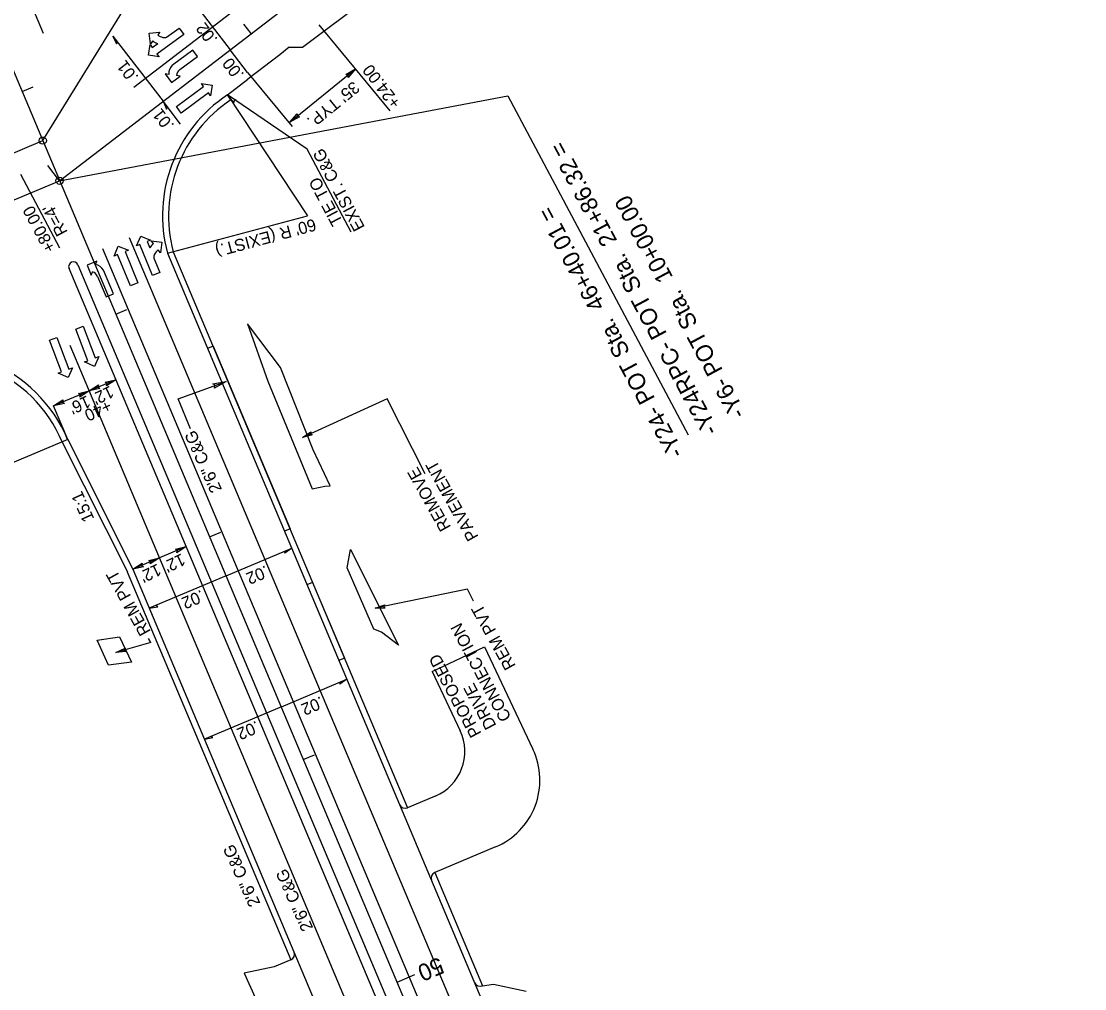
# Model space of a CAD drawing. Extents: x 2389694 to 2405615, y 546931 to 573532.
# Drawn here: x 2402756.3 to 2403196.8, y 570052.9 to 570453.5 of the extents above; entities that cross this region are included whole.
import ezdxf

# ---------------------------------------------------------------- set-up
doc = ezdxf.new("R2010")
doc.units = 0
for name, color, linetype in [('Old_Level_11', 7, 'Continuous'), ('Old_Level_3', 7, 'Continuous'), ('Prop Conc 2ft 6in Curb and Gutter', 7, 'Continuous'), ('Prop Conc 5in Monolithic Keyed In Island', 7, 'Continuous'), ('Prop Dimension', 7, 'Continuous'), ('Prop Dimension Text', 7, 'Continuous'), ('Prop DSN Text', 7, 'Continuous'), ('Prop EOT', 7, 'Continuous'), ('Prop Hatching', 7, 'Continuous'), ('Prop Horizontal Alignment', 7, 'Continuous'), ('Prop Horizontal Alignment Curve and Spiral Data', 7, 'Continuous'), ('Prop Horizontal Alignment Tick Large', 7, 'Continuous'), ('Prop Horizontal Alignment Tick Small', 7, 'Continuous'), ('Prop Lane Arrow Left Turn CELL', 7, 'Continuous'), ('Prop Lane Arrow Shared Rt and Thru CELL', 7, 'Continuous'), ('Prop Lane Arrow Through CELL', 7, 'Continuous'), ('Prop Lane Lines', 7, 'Continuous'), ('Prop Super Arrow 1 Lane CELL', 7, 'Continuous'), ('Prop Superelevation Label', 7, 'Continuous')]:
    doc.layers.add(name, color=color, linetype=linetype)

# ---------------------------------------------------------------- blocks, each defined once
blk = doc.blocks.new('TERM')
at = {"layer": 'Old_Level_11'}
blk.add_lwpolyline([(-0.01375, 0.00225), (0, 0), (-0.01375, -0.0025), (-0.012, 0)], close=True, dxfattribs=at)

msp = doc.modelspace()

# ---------------------------------------------------------------- linework, layer by layer
at = {"layer": 'Old_Level_3'}
for p, q in [((2402819.33, 570358.05), (2402916.31, 570127.82)), ((2402927.62, 570100.99), (2402947.36, 570054.13))]:
    msp.add_line(p, q, dxfattribs=at)
for centre, radius, start, end in [((2402874.85, 570372.92), 57.5, 123.4608, 194.9966), ((2402867.01, 570067.13), 2.5, 293.3106, 22.8448), ((2402946.41, 570056.44), 2.5, 202.8448, 292.379)]:
    msp.add_arc(centre, radius, start, end, dxfattribs=at)
at = {"layer": 'Prop Conc 2ft 6in Curb and Gutter'}
for p, q in [((2402843.14, 570420.89), (2402841.76, 570422.97)), ((2402835.78, 570318.99), (2402833.48, 570318.01)), ((2402835.78, 570318.99), (2402867.66, 570243.32)), ((2402773.33, 570279.21), (2402800.31, 570225.49)), ((2402867.66, 570243.32), (2402865.35, 570242.35)), ((2402800.27, 570225.56), (2402867.98, 570064.82)), ((2402877, 570221.15), (2402874.69, 570220.18)), ((2402877, 570221.15), (2402889.21, 570192.16)), ((2402890.22, 570189.76), (2402887.92, 570188.79)), ((2402889.21, 570192.16), (2402890.22, 570189.76))]:
    msp.add_line(p, q, dxfattribs=at)
msp.add_arc((2402720.27, 570257.04), 57.5, 22.8448, 112.8448, dxfattribs=at)
at = {"layer": 'Prop Conc 5in Monolithic Keyed In Island'}
for p, q in [((2402779.82, 570352.67), (2402944.82, 569961)), ((2402941.22, 569959.23), (2402776.13, 570351.12)), ((2402776.13, 570351.12), (2402776.13, 570351.12))]:
    msp.add_line(p, q, dxfattribs=at)
msp.add_arc((2402777.97, 570351.89), 2, 22.8448, 202.8424, dxfattribs=at)
at = {"layer": 'Prop Dimension'}
for p, q in [((2402879.62, 570452.02), (2402909.05, 570416.43)), ((2402850.07, 570432.19), (2402868.5, 570409.89)), ((2402867.6, 570411.63), (2402894.77, 570433.7)), ((2402841.76, 570422.97), (2402874.85, 570372.92)), ((2402874.73, 570400.48), (2402841.76, 570422.97)), ((2402893, 570366.11), (2402874.73, 570400.48)), ((2402816.89, 570357.39), (2402874.85, 570372.92)), ((2402795.54, 570305.04), (2402769.74, 570294.17)), ((2402821.34, 570297.09), (2402841.23, 570304.38)), ((2402826.5, 570284.66), (2402821.34, 570297.09)), ((2402907.87, 570297.12), (2402872.83, 570281.13)), ((2402923.7, 570266.05), (2402907.87, 570297.12)), ((2402775.57, 570280.33), (2402769.74, 570294.17)), ((2402775.57, 570280.33), (2402720.27, 570257.04)), ((2402824.66, 570235.93), (2402802.54, 570226.61)), ((2402941.22, 570218.32), (2402902.95, 570210.43)), ((2402943.73, 570213.38), (2402941.22, 570218.32)), ((2402809.99, 570196.22), (2402795.56, 570192.14)), ((2402809.99, 570196.22), (2402809.11, 570197.96))]:
    msp.add_line(p, q, dxfattribs=at)
for points in [[(2402890.79, 570431.46), (2402894.77, 570433.7), (2402891.76, 570430.23), (2402891.71, 570431.21)], [(2402871.59, 570413.87), (2402867.6, 570411.63), (2402870.61, 570415.1), (2402870.67, 570414.12)], [(2402791.09, 570304), (2402795.54, 570305.04), (2402791.68, 570302.54), (2402791.9, 570303.5)], [(2402780.03, 570299.34), (2402784.48, 570300.38), (2402780.62, 570297.88), (2402780.84, 570298.84)], [(2402788.93, 570301.41), (2402784.48, 570300.38), (2402788.34, 570302.87), (2402788.12, 570301.91)], [(2402774.19, 570295.2), (2402769.74, 570294.17), (2402773.6, 570296.66), (2402773.38, 570295.7)], [(2402820.21, 570234.89), (2402824.66, 570235.93), (2402820.8, 570233.43), (2402821.02, 570234.39)], [(2402809.15, 570230.23), (2402813.6, 570231.27), (2402809.74, 570228.77), (2402809.96, 570229.73)], [(2402806.99, 570227.64), (2402802.54, 570226.61), (2402806.4, 570229.1), (2402806.18, 570228.14)]]:
    msp.add_lwpolyline(points, close=True, dxfattribs=at)
at = {"layer": 'Prop DSN Text'}
msp.add_line((2402756, 570390.09), (2402772.15, 570359.72), dxfattribs=at)
at = {"layer": 'Prop EOT'}
for p, q in [((2402872.9, 570442.74), (2402906.33, 570467.95)), ((2402867.32, 570442.76), (2402863.42, 570439.53)), ((2402867.32, 570442.76), (2402872.9, 570442.74)), ((2402863.42, 570439.53), (2402850.26, 570429.48)), ((2402841.76, 570422.97), (2402850.26, 570429.48)), ((2402816.89, 570357.39), (2403055.64, 569790.67)), ((2402775.57, 570280.33), (2402802.54, 570226.61)), ((2402802.54, 570226.61), (2403006.37, 569742.78)), ((2402926.55, 570184.23), (2402948.25, 570194.48)), ((2402948.25, 570194.48), (2402968.29, 570152.08)), ((2402926.55, 570184.23), (2402938.16, 570159.66)), ((2402927.84, 570132.68), (2402916.3, 570127.82)), ((2402952.82, 570111.61), (2402927.6, 570100.98)), ((2402861.07, 570061.91), (2402848.71, 570059.37)), ((2402868, 570064.83), (2402861.07, 570061.91)), ((2402848.71, 570059.37), (2402855.91, 570043.46)), ((2402947.36, 570054.13), (2402951.96, 570054.8)), ((2402951.96, 570054.8), (2402965.52, 570051.88))]:
    msp.add_line(p, q, dxfattribs=at)
for centre, radius, start, end in [((2402874.85, 570372.92), 60, 123.4608, 194.9966), ((2402720.27, 570257.04), 60, 22.8448, 112.8448), ((2402920.08, 570151.11), 20, 292.8445, 25.3014), ((2402941.17, 570139.25), 30, 292.8448, 25.3014), ((2402915.34, 570130.13), 2.5, 202.8448, 292.379), ((2402928.59, 570098.69), 2.5, 113.3106, 202.8448), ((2402867.01, 570067.13), 2.5, 293.3106, 22.8448)]:
    msp.add_arc(centre, radius, start, end, dxfattribs=at)
at = {"layer": 'Prop Hatching'}
for points in [[(2402850.11, 570328.19), (2402858.48, 570304.42), (2402876.83, 570259.87), (2402882.14, 570261.03), (2402884.25, 570261.17), (2402877.26, 570276.04), (2402863.68, 570310.07)], [(2402892.74, 570234.74), (2402912.6, 570195.15), (2402905.5, 570200.55), (2402902.4, 570201.76), (2402891.31, 570227.18)], [(2402787.83, 570197.16), (2402797.01, 570198.66), (2402802.01, 570188.07), (2402792.51, 570186.81)]]:
    msp.add_lwpolyline(points, close=True, dxfattribs=at)
at = {"layer": 'Prop Horizontal Alignment'}
for p, q in [((2402772.22, 570387.43), (2404675.94, 571848.89)), ((2402590.46, 570818.88), (2403091.06, 569630.61)), ((2402624.75, 570344.84), (2402765.23, 570404.03)), ((2402579.23, 570306.13), (2402772.22, 570387.44))]:
    msp.add_line(p, q, dxfattribs=at)
at = {"layer": 'Prop Horizontal Alignment Curve and Spiral Data'}
for p, q in [((2402765.23, 570404.03), (2402845.57, 570534.22)), ((2402772.22, 570387.44), (2402957.95, 570422.61)), ((2402957.95, 570422.61), (2403032.57, 570282.26))]:
    msp.add_line(p, q, dxfattribs=at)
for centre in [(2402765.23, 570404.03), (2402772.22, 570387.44), (2402772.22, 570387.43)]:
    msp.add_circle(centre, 1.5, dxfattribs=at)
at = {"layer": 'Prop Horizontal Alignment Tick Large'}
for p, q in [((2402772.22, 570387.43), (2402767.35, 570393.78)), ((2402911.98, 570055.68), (2402919.36, 570058.79))]:
    msp.add_line(p, q, dxfattribs=at)
at = {"layer": 'Prop Horizontal Alignment Tick Small'}
for p, q in [((2402851.55, 570448.33), (2402848.5, 570452.29)), ((2402756.69, 570424.31), (2402761.3, 570426.25)), ((2402795.51, 570332.15), (2402800.12, 570334.09)), ((2402834.34, 570240), (2402838.94, 570241.94)), ((2402873.16, 570147.84), (2402877.77, 570149.78))]:
    msp.add_line(p, q, dxfattribs=at)
at = {"layer": 'Prop Lane Arrow Left Turn CELL'}
for p, q in [((2402827.36, 570441.55), (2402818.92, 570435.22)), ((2402829.34, 570438.91), (2402827.36, 570441.55)), ((2402822.02, 570433.42), (2402829.34, 570438.91)), ((2402817.42, 570431.47), (2402815.95, 570431.68)), ((2402815.95, 570431.68), (2402818.55, 570428.13)), ((2402818.55, 570428.13), (2402822.18, 570430.79)), ((2402822.18, 570430.79), (2402820.71, 570431)), ((2402787.67, 570354.12), (2402783.6, 570352.45)), ((2402783.6, 570352.45), (2402785.31, 570348.28)), ((2402787.11, 570352.74), (2402787.67, 570354.12)), ((2402785.31, 570348.28), (2402785.87, 570349.66)), ((2402794.51, 570340.67), (2402790.39, 570350.38)), ((2402787.9, 570347.81), (2402791.47, 570339.38)), ((2402791.47, 570339.38), (2402794.51, 570340.67))]:
    msp.add_line(p, q, dxfattribs=at)
for centre, radius, start, end in [((2402822.66, 570431.55), 5.25, 135.5473, 180.859), ((2402823.97, 570430.81), 3.28, 126.8712, 176.5294), ((2402785.94, 570347.64), 5.25, 31.6428, 76.9545), ((2402784.9, 570346.55), 3.27, 22.9668, 72.625)]:
    msp.add_arc(centre, radius, start, end, dxfattribs=at)
at = {"layer": 'Prop Lane Arrow Shared Rt and Thru CELL'}
for p, q in [((2402816.56, 570446.87), (2402821.79, 570450.65)), ((2402821.79, 570450.65), (2402823.72, 570447.97)), ((2402809.38, 570448.53), (2402813.78, 570449)), ((2402809.85, 570444.12), (2402809.38, 570448.53)), ((2402810.79, 570445.29), (2402809.85, 570444.12)), ((2402823.72, 570447.97), (2402812.53, 570439.89)), ((2402813.78, 570449), (2402812.88, 570447.85)), ((2402809.05, 570439.41), (2402809.72, 570443.78)), ((2402809.72, 570443.78), (2402810.6, 570442.56)), ((2402810.6, 570442.56), (2402812.91, 570444.23)), ((2402813.41, 570438.67), (2402809.05, 570439.41)), ((2402812.53, 570439.89), (2402813.41, 570438.67)), ((2402804.06, 570360.42), (2402805.81, 570364.48)), ((2402805.81, 570364.48), (2402809.9, 570362.8)), ((2402809.9, 570362.8), (2402808.51, 570362.23)), ((2402808.51, 570362.23), (2402809.58, 570359.59)), ((2402811.11, 570361.4), (2402810.2, 570362.59)), ((2402810.2, 570362.59), (2402814.59, 570362.01)), ((2402814.59, 570362.01), (2402814.01, 570357.61)), ((2402805.45, 570360.99), (2402804.06, 570360.42)), ((2402810.66, 570348.21), (2402805.45, 570360.99)), ((2402814.01, 570357.61), (2402813.11, 570358.76)), ((2402811.28, 570355.42), (2402813.71, 570349.45)), ((2402813.71, 570349.45), (2402810.66, 570348.21))]:
    msp.add_line(p, q, dxfattribs=at)
for centre, radius, start, end in [((2402813.79, 570448.56), 4.43, 227.4438, 258.3224), ((2402815.88, 570451.13), 4.43, 227.5626, 258.4162), ((2402815.65, 570449.22), 2.52, 254.9261, 291.2381), ((2402813.58, 570357.71), 4.43, 123.7571, 154.6357), ((2402813.78, 570355.75), 2.52, 151.2393, 187.5513), ((2402815.58, 570355.08), 4.43, 123.8759, 154.7294)]:
    msp.add_arc(centre, radius, start, end, dxfattribs=at)
at = {"layer": 'Prop Lane Arrow Through CELL'}
for p, q in [((2402831.89, 570426.42), (2402831, 570427.63)), ((2402831, 570427.63), (2402835.37, 570427)), ((2402820.61, 570418.12), (2402831.89, 570426.42)), ((2402833.84, 570423.76), (2402822.57, 570415.46)), ((2402834.73, 570422.55), (2402833.84, 570423.76)), ((2402835.37, 570427), (2402834.73, 570422.55)), ((2402822.57, 570415.46), (2402820.61, 570418.12)), ((2402794.89, 570356.26), (2402796.55, 570360.36)), ((2402796.55, 570360.36), (2402800.71, 570358.66)), ((2402800.71, 570358.66), (2402799.33, 570358.09)), ((2402799.33, 570358.09), (2402804.67, 570345.15)), ((2402796.27, 570356.83), (2402794.89, 570356.26)), ((2402801.62, 570343.89), (2402796.27, 570356.83)), ((2402804.67, 570345.15), (2402801.62, 570343.89)), ((2402778.95, 570326.01), (2402782.04, 570327.18)), ((2402782.04, 570327.18), (2402787.02, 570314.1)), ((2402768.04, 570321.39), (2402771.12, 570322.56)), ((2402771.12, 570322.56), (2402776.11, 570309.48)), ((2402783.94, 570312.92), (2402778.95, 570326.01)), ((2402773.02, 570308.31), (2402768.04, 570321.39)), ((2402782.54, 570312.39), (2402783.94, 570312.92)), ((2402788.42, 570314.63), (2402786.65, 570310.59)), ((2402787.02, 570314.1), (2402788.42, 570314.63)), ((2402777.51, 570310.02), (2402775.73, 570305.97)), ((2402776.11, 570309.48), (2402777.51, 570310.02)), ((2402786.65, 570310.59), (2402782.54, 570312.39)), ((2402771.62, 570307.77), (2402773.02, 570308.31)), ((2402775.73, 570305.97), (2402771.62, 570307.77))]:
    msp.add_line(p, q, dxfattribs=at)
at = {"layer": 'Prop Lane Lines'}
for p, q in [((2402513.78, 571045.89), (2402765.48, 570448.53)), ((2402802.99, 570426.19), (2403161.53, 570701.43)), ((2402801.09, 570363.98), (2403049.05, 569775.41)), ((2402790.03, 570359.32), (2402994.7, 569873.51)), ((2402776.49, 570319.35), (2403017.42, 569747.44))]:
    msp.add_line(p, q, dxfattribs=at)
at = {"layer": 'Prop Super Arrow 1 Lane CELL'}
for p, q in [((2402827.1, 570462.11), (2402842.82, 570441.63)), ((2402794.33, 570447.31), (2402815.06, 570420.32)), ((2402850.07, 570432.19), (2402842.82, 570441.63)), ((2402822.31, 570410.87), (2402815.06, 570420.32)), ((2402841.24, 570223.83), (2402868.41, 570235.28)), ((2402841.24, 570223.83), (2402809.37, 570210.4)), ((2402864.07, 570169.65), (2402891.24, 570181.09)), ((2402864.07, 570169.65), (2402832.19, 570156.22))]:
    msp.add_line(p, q, dxfattribs=at)
for points in [[(2402794.33, 570447.31), (2402795.83, 570444.05), (2402796.13, 570444.97)], [(2402815.06, 570420.32), (2402816.55, 570417.05), (2402816.85, 570417.98)], [(2402868.41, 570235.28), (2402865.49, 570233.18), (2402865.69, 570234.13)], [(2402809.37, 570210.4), (2402812.9, 570211.03), (2402812.08, 570211.55)], [(2402891.24, 570181.09), (2402888.32, 570179), (2402888.52, 570179.95)], [(2402832.19, 570156.22), (2402835.73, 570156.85), (2402834.91, 570157.37)]]:
    msp.add_lwpolyline(points, close=True, dxfattribs=at)

# ---------------------------------------------------------------- block references
at = {"layer": 'Prop Dimension'}
for p, xscale, yscale, rotation in [((2402841.76, 570422.97), 300, 299.99999999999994, 139.09786117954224), ((2402841.23, 570304.38), 400.00000000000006, 400, 20.125180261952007), ((2402872.83, 570281.13), 300, 300, -155.4717133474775), ((2402902.95, 570210.43), 300.00000000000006, 300.0000000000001, -169.63788284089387), ((2402795.56, 570192.14), 299.99999999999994, 300.00000000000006, -164.79801089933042)]:
    msp.add_blockref('TERM', p, dxfattribs=dict(at, xscale=xscale, yscale=yscale, rotation=rotation))

# ---------------------------------------------------------------- texts
at = {"layer": 'Prop Dimension Text'}
for s, rotation, p in [("35' TYP.", 219.1342, (2402893.91, 570428.91)), ('EXIST. C&G', 117.9326, (2402898.8, 570368.21)), ('TIE TO ', 117.9326, (2402889.7, 570370.43)), ("60' R (EXIST.)", 195.1141, (2402877.69, 570371.79)), ("12'", 205.5034, (2402793.13, 570302.71)), ("16'", 204.3161, (2402783.57, 570298.66)), ('+40', 204.3161, (2402792.35, 570296.84)), ('2\'6" C&G', 114.2804, (2402839.58, 570259.6)), ('REMOVE', 119.1108, (2402934.47, 570244.02)), ('PAVEMENT', 119.1108, (2402945.86, 570240)), ('15:1', 114.2058, (2402786.69, 570247.49)), ("12'", 205.5034, (2402822.76, 570233.27)), ('REM PVT', 119.1108, (2402810.08, 570200.78)), ("12'", 205.5034, (2402812.79, 570229.05)), ('REM PVT', 119.1108, (2402961.33, 570186.61)), ('2\'6" C&G', 114.2804, (2402855.49, 570088.21)), ('2\'6" C&G', 114.2804, (2402877.37, 570078.07))]:
    msp.add_text(s, height=5, rotation=rotation, dxfattribs=at).set_placement(p)
at = {"layer": 'Prop DSN Text'}
for s, p in [('+80.00', (2402770.81, 570359.39)), ("R=4'", (2402775.7, 570366.16)), ('CONNECTION', (2402959.46, 570165.16)), ('PROPOSED', (2402947.1, 570158.59)), ('DRIVE', (2402953.28, 570161.87))]:
    msp.add_text(s, height=5, rotation=118, dxfattribs=at).set_placement(p)
at = {"layer": 'Prop Horizontal Alignment Curve and Spiral Data'}
for s, rotation, p in [('-Y24RPC- POT Sta.  21+86.32 =', 118.1555, (2403045.29, 570284.19)), ('-Y6- POT Sta.  10+00.00', 118.1555, (2403056.66, 570291.09)), ('-Y24- POT Sta.  46+40.01 =', 118.1555, (2403031.04, 570274.75)), ('50', 202.8448, (2402929.46, 570066.18))]:
    msp.add_text(s, height=7, rotation=rotation, dxfattribs=at).set_placement(p)
at = {"layer": 'Prop Superelevation Label'}
for s, rotation, p in [('.02', 127.5133, (2402837.95, 570446.05)), ('.01', 127.5133, (2402805.18, 570430.43)), ('.00', 127.5133, (2402848.86, 570431.5)), ('+24.00', 127.5133, (2402913.86, 570419.74)), ('.01', 127.5133, (2402819.94, 570410.45)), ('.02', 202.8452, (2402857.55, 570228.28)), ('.02', 202.8452, (2402830.88, 570218.12)), ('.02', 202.8452, (2402880.38, 570174.09)), ('.02', 202.8452, (2402853.71, 570163.93))]:
    msp.add_text(s, height=5, rotation=rotation, dxfattribs=at).set_placement(p)

doc.saveas('drawing.dxf')
